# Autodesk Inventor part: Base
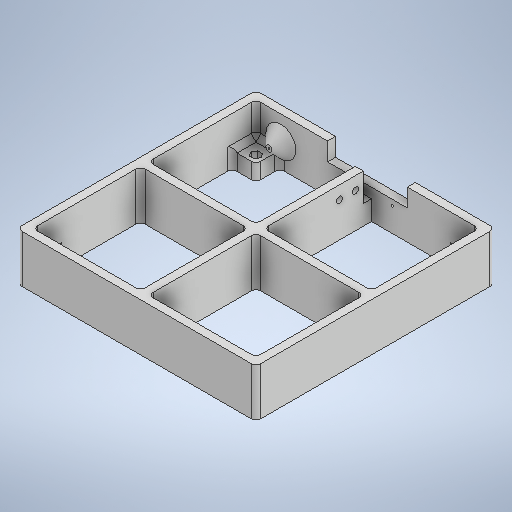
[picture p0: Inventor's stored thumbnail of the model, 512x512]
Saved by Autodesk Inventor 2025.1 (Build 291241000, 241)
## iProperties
Created: 2023-12
Part Number: Base
Material: Generic
Document SubType Name: Modeling
Designer: Andrew
Density: 1 g/cm^3
Appearance: Default
Author: Andrew
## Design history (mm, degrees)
sketch "Sketch1"
  geometry: L1 (76.2, -76.2)-(-76.2, -76.2); L2 (-76.2, -76.2)-(-76.2, 76.2); L3 (-76.2, 76.2)-(76.2, 76.2); L4 (76.2, 76.2)-(76.2, -76.2); 1 further point
  constraints: 8 end point, 2 parallel, 1 horizontal, 1 perpendicular
  dimensions: "d0" = 152.4 distance between parallel lines of L3 L1 (derived); "d1" = 152.4 distance between parallel lines of L4 L2; "d2" = 76.2 distance from line of point (0, 0) L1 (= 0.5 x d0); "d3" = 76.2 distance from line of L2 point (0, 0) (= 0.5 x d1)
extrude "Extrusion1" new body sketch "Sketch1" distance "d4" = 5.08; taper "d5" = 0 deg
sketch "Sketch2"
  geometry: L1 (-76.2, -76.2)-(76.2, -76.2) reference; L2 (76.2, -76.2)-(76.2, 76.2) reference; L3 (76.2, 76.2)-(-76.2, 76.2) reference; L4 (-76.2, 76.2)-(-76.2, -76.2) reference; L5 (-71.12, 71.12)-(71.12, 71.12); L6 (71.12, 71.12)-(71.12, -71.12); L7 (71.12, -71.12)-(-71.12, -71.12); L8 (-71.12, -71.12)-(-71.12, 71.12); L9 (-71.12, 2.54)-(71.12, 2.54); L10 (71.12, 2.54)-(71.12, -2.54); L11 (71.12, -2.54)-(-71.12, -2.54); L12 (-71.12, -2.54)-(-71.12, 2.54); L13 (-2.54, 71.12)-(2.54, 71.12); L14 (2.54, 71.12)-(2.54, -71.12); L15 (2.54, -71.12)-(-2.54, -71.12); L16 (-2.54, -71.12)-(-2.54, 71.12); 11 further points
  constraints: 24 end point, 6 parallel, 4 point on line, 3 horizontal, 3 perpendicular, 2 midpoint
  dimensions: "d6" = 5.08 distance between parallel lines of L5 L3; "d7" = 5.08 distance between parallel lines of L4 L8; "d8" = 5.08 distance between parallel lines of L2 L6; "d9" = 5.08 distance between parallel lines of L1 L7; "d10" = 5.08 distance between parallel lines of L11 L9; "d11" = 5.08 distance between parallel lines of L16 L14; "d207" = 152.4 distance between parallel lines of L1 L3 (derived); "d208" = 76.2 distance from line of L1 point (-71.12, 0) (derived); "d209" = 76.2 distance from line of point (0, -71.12) L4 (derived)
extrude "Extrusion2" join sketch "Sketch2" distance "d14" = 25.4; taper "d15" = 0 deg
sketch "Sketch3"
  geometry: L1 (0, 30.48)-(152.4, 30.48) reference; L2 (104.14, 30.48)-(93.98, 30.48); L3 (93.98, 30.48)-(93.98, -19.05); L4 (93.98, -19.05)-(104.14, -19.05); L5 (104.14, -19.05)-(104.14, 30.48); L6 (58.42, 30.48)-(48.26, 30.48); L7 (48.26, 30.48)-(48.26, -19.05); L8 (48.26, -19.05)-(58.42, -19.05); L9 (58.42, -19.05)-(58.42, 30.48); L10 (152.4, 0)-(152.4, 30.48) reference; L11 (0, 0)-(152.4, 0) reference; 7 further points
  constraints: 16 end point, 5 midpoint, 4 parallel, 3 point on line, 2 horizontal, 2 perpendicular
  dimensions: "d18" = 10.16 distance from line of L3 point (104.14, 5.715); "d19" = 10.16 distance from line of L7 point (58.42, 5.715); "d20" = 35.56 distance between parallel lines of L9 L3; "d173" = 19.05 distance between parallel lines of L11 L4; "d198" = 17.78 distance from line of point (76.2, 30.48) L3 (derived)
extrude "Extrusion3" join sketch "Sketch3" distance "d23" = 38.1; taper "d24" = 0 deg
sketch "Sketch4"
  geometry: L1 (93.98, 30.48)-(93.98, -19.05) reference; L2 (93.98, 25.4)-(58.42, 25.4); L3 (58.42, 25.4)-(58.42, 30.48); L4 (58.42, 30.48)-(93.98, 30.48); L5 (93.98, 30.48)-(93.98, 25.4); L6 (58.42, -19.05)-(58.42, 30.48) reference; L7 (58.42, 30.48)-(93.98, 30.48) reference; 2 further points
  constraints: 8 end point, 2 parallel, 1 horizontal, 1 perpendicular, 1 point on line
  dimensions: "d25" = 0 distance between parallel lines of L6 L3; "d26" = 0 distance between parallel lines of L7 L4; "d27" = 5.08 distance between parallel lines of L4 L2
extrude "Extrusion4" join sketch "Sketch4" stored distance "d28" = 25.4; taper "d29" = 0 deg
sketch "Sketch5"
  geometry: L1 (7.62, -33.02)-(48.26, -33.02); L2 (48.26, -33.02)-(48.26, 0); L3 (48.26, 0)-(7.62, 0); L4 (7.62, 0)-(7.62, -33.02); L5 (104.14, 0)-(-48.26, 0) reference; L6 (10.16, -38.1)-(0, -38.1) reference; L7 (45.72, -38.1)-(10.16, -38.1) reference; 6 further points; 2 other entities
  constraints: 8 end point, 2 parallel, 1 horizontal, 1 midpoint, 1 perpendicular, 2 other
  dimensions: "d32" = 33.02 distance between parallel lines of L1 L3; "d174" = 2.54 dimension on L4; "d175" = 2.54 dimension on L2; "d177" = 38.1 distance between parallel lines of L6 L3
extrude "Extrusion5" cut sketch "Sketch5" distance "d34" = 2.54; taper "d35" = 0 deg
sketch "Sketch8"
  geometry: L1 (55.88, 25.4)-(96.52, 25.4); L2 (96.52, 25.4)-(96.52, 19.812); L3 (96.52, 19.812)-(55.88, 19.812); L4 (55.88, 19.812)-(55.88, 25.4); L5 (58.42, -19.05)-(58.42, 25.4) reference; L6 (93.98, 25.4)-(93.98, -19.05) reference; L7 (96.52, 11.684)-(55.88, 11.684); L8 (55.88, 11.684)-(55.88, 17.272); L9 (55.88, 17.272)-(96.52, 17.272); L10 (96.52, 17.272)-(96.52, 11.684); L11 (96.52, 3.556)-(55.88, 3.556); L12 (55.88, 3.556)-(55.88, 9.144); L13 (55.88, 9.144)-(96.52, 9.144); L14 (96.52, 9.144)-(96.52, 3.556); L15 (96.52, -4.572)-(55.88, -4.572); L16 (55.88, -4.572)-(55.88, 1.016); L17 (55.88, 1.016)-(96.52, 1.016); L18 (96.52, 1.016)-(96.52, -4.572); L19 (96.52, -12.7)-(55.88, -12.7); L20 (55.88, -12.7)-(55.88, -7.112); L21 (55.88, -7.112)-(96.52, -7.112); L22 (96.52, -7.112)-(96.52, -12.7); L23 (96.52, -15.24)-(55.88, -15.24); L24 (55.88, -15.24)-(55.88, -20.828); L25 (55.88, -20.828)-(96.52, -20.828); L26 (96.52, -20.828)-(96.52, -15.24); L27 (96.52, -28.956)-(55.88, -28.956); L28 (55.88, -28.956)-(55.88, -23.368); L29 (55.88, -23.368)-(96.52, -23.368); L30 (96.52, -23.368)-(96.52, -28.956); L31 (96.52, -37.084)-(55.88, -37.084); L32 (55.88, -37.084)-(55.88, -31.496); L33 (55.88, -31.496)-(96.52, -31.496); L34 (96.52, -31.496)-(96.52, -37.084); 15 further points
  constraints: 64 end point, 16 parallel, 13 collinear, 8 horizontal, 8 perpendicular, 2 midpoint, 2 other
  dimensions: "d39" = 5.588 dimension on L3; "d40" = 2.54 distance between parallel lines of L5 L4; "d41" = 2.54 distance between parallel lines of L6 L2; "d117" = 5.588 distance between parallel lines of L9 L7 (= d39); "d119" = 2.54 distance between parallel lines of L3 L9; "d120" = 2.54 distance between parallel lines of L7 L13 (= d119); "d121" = 5.588 distance between parallel lines of L13 L11 (= d117); "d122" = 5.588 distance between parallel lines of L17 L15 (= d121); "d123" = 2.54 distance between parallel lines of L11 L17 (= d120); "d178" = 5.588 distance between parallel lines of L21 L19 (derived); "d179" = 2.54 distance between parallel lines of L15 L21 (derived); "d180" = 5.588 distance from line of point (76.2, -15.24) L25 (derived); "d181" = 2.54 distance between parallel lines of L19 L23 (derived); "d199" = 2.54 distance from line of point (55.88, -18.034) L5 (derived); "d200" = 5.588 distance between parallel lines of L29 L27 (derived); "d201" = 5.588 distance between parallel lines of L33 L31 (derived); "d202" = 2.54 distance between parallel lines of L25 L29 (derived); "d203" = 2.54 distance between parallel lines of L27 L33 (derived)
extrude "Extrusion7" cut sketch "Sketch8" stored distance "d42" = 31.75; taper "d43" = 0 deg
fillet "Fillet1" dims "d49" = 3.175
sketch "Sketch10"
  geometry: L1 (2.54, -2.54)-(71.12, -2.54) reference; L2 (71.12, -2.54)-(71.12, -71.12) reference; L3 (71.12, -71.12)-(2.54, -71.12) reference; L4 (2.54, -71.12)-(2.54, -2.54) reference; L5 (71.12, 71.12)-(2.54, 71.12) reference; L6 (2.54, 2.54)-(2.54, 71.12) reference; L7 (2.54, 71.12)-(71.12, 71.12) reference; L8 (71.12, 71.12)-(71.12, 2.54) reference; L9 (71.12, 2.54)-(2.54, 2.54) reference; L10 (-2.54, 2.54)-(-71.12, 2.54) reference; L11 (-71.12, 2.54)-(-71.12, 71.12) reference; L12 (-71.12, 71.12)-(-2.54, 71.12) reference; L13 (-2.54, 71.12)-(-2.54, 2.54) reference; L14 (-2.54, -2.54)-(-2.54, -71.12) reference; L15 (-2.54, -71.12)-(-71.12, -71.12) reference; L16 (-71.12, -71.12)-(-71.12, -2.54) reference; L17 (-71.12, -2.54)-(-2.54, -2.54) reference; 3 further points
extrude "Extrusion9" cut sketch "Sketch10" distance "d54" = 25.4; taper "d55" = 0 deg
sketch "Sketch12" dims "d175" = 2.54
  geometry: L1 (2.54, 71.12)-(71.12, 71.12) reference; L2 (71.12, 71.12)-(55.88, 71.12); L3 (55.88, 71.12)-(55.88, 55.88); L4 (55.88, 55.88)-(71.12, 55.88); L5 (71.12, 55.88)-(71.12, 71.12); L6 (71.12, -71.12)-(2.54, -71.12) reference; L7 (71.12, -71.12)-(55.88, -71.12); L8 (55.88, -71.12)-(55.88, -55.88); L9 (55.88, -55.88)-(71.12, -55.88); L10 (71.12, -55.88)-(71.12, -71.12); L11 (-71.12, 71.12)-(-55.88, 71.12); L12 (-55.88, 71.12)-(-55.88, 55.88); L13 (-55.88, 55.88)-(-71.12, 55.88); L14 (-71.12, 55.88)-(-71.12, 71.12); L15 (-71.12, -71.12)-(-71.12, -2.54) reference; L16 (-71.12, -71.12)-(-55.88, -71.12); L17 (-55.88, -71.12)-(-55.88, -55.88); L18 (-55.88, -55.88)-(-71.12, -55.88); L19 (-71.12, -55.88)-(-71.12, -71.12); L20 (71.12, -2.54)-(71.12, -71.12) reference; L21 (-71.12, 2.54)-(-71.12, 71.12) reference; L22 (71.12, 71.12)-(71.12, 2.54) reference; L23 (76.2, 73.025)-(76.2, -73.025) reference; L24 (-76.2, -73.025)-(-76.2, 73.025) reference; L25 (-73.025, 76.2)-(73.025, 76.2) reference; C1 r 1.905 at (60.96, 60.96); C2 r 1.905 at (60.96, -60.96); C3 r 1.905 at (-60.96, 60.96); C4 r 1.905 at (-60.96, -60.96); 17 further points; 2 other entities
  constraints: 32 end point, 8 parallel, 6 midpoint, 4 centre point, 4 horizontal, 4 perpendicular, 2 other
  dimensions: "d56" = 15.24 distance between parallel lines of L6 L9 (= d82); "d57" = 15.24 distance between parallel lines of L20 L8 (= d58); "d58" = 15.24 distance from line of L15 point (-55.88, -63.5); "d59" = 15.24 distance from line of L16 point (-63.5, -55.88); "d64" = 3.81 diameter of C3; "d65" = 3.81 diameter of C4 (= d64); "d66" = 3.81 diameter of C2 (= d64); "d67" = 3.81 diameter of C1 (= d64); "d78" = 15.24 dimension on C2.centre; "d79" = 15.24 distance from line of L23 C2.centre; "d85" = 15.24 distance from line of point (63.5, 71.12) L4 (= d78); "d86" = 15.24 distance between parallel lines of L5 L3 (= d57); "d87" = 15.24 distance between parallel lines of L14 L12 (= d82); "d88" = 15.24 distance between parallel lines of L13 L11 (= d58); "d89" = 15.24 distance from line of C3.centre L25 (= d82); "d90" = 15.24 dimension on C4.centre (= d78); "d91" = 15.24 distance from line of L24 C4.centre (= d79); "d92" = 15.24 distance from line of L24 C3.centre (= d58); "d93" = 15.24 distance from line of L23 C1.centre (= d57); "d94" = 15.24 distance from line of L25 C1.centre (= d78)
extrude "Extrusion10" join sketch "Sketch12" stored distance "d76" = 25.4; taper "d77" = 0 deg
fillet "Fillet2" dims "d95" = 3.175
sketch "Sketch13"
  geometry: L1 (-62.544, -58.217)-(-59.376, -58.217); L2 (-59.376, -58.217)-(-57.792, -60.96); L3 (-57.792, -60.96)-(-59.376, -63.703); L4 (-59.376, -63.703)-(-62.544, -63.703); L5 (-62.544, -63.703)-(-64.128, -60.96); L6 (-64.128, -60.96)-(-62.544, -58.217); L7 (-59.376, 63.703)-(-57.792, 60.96); L8 (-57.792, 60.96)-(-59.376, 58.217); L9 (-59.376, 58.217)-(-62.544, 58.217); L10 (-62.544, 58.217)-(-64.128, 60.96); L11 (-64.128, 60.96)-(-62.544, 63.703); L12 (-62.544, 63.703)-(-59.376, 63.703); L13 (59.376, 63.703)-(62.544, 63.703); L14 (62.544, 63.703)-(64.128, 60.96); L15 (64.128, 60.96)-(62.544, 58.217); L16 (62.544, 58.217)-(59.376, 58.217); L17 (59.376, 58.217)-(57.792, 60.96); L18 (57.792, 60.96)-(59.376, 63.703); L19 (59.376, -58.217)-(62.544, -58.217); L20 (62.544, -58.217)-(64.128, -60.96); L21 (64.128, -60.96)-(62.544, -63.703); L22 (62.544, -63.703)-(59.376, -63.703); L23 (59.376, -63.703)-(57.792, -60.96); L24 (57.792, -60.96)-(59.376, -58.217); C1 r 1.905 at (-60.96, -60.96) reference; C2 r 1.905 at (-60.96, 60.96) reference; C3 r 1.905 at (60.96, 60.96) reference; C4 r 1.905 at (60.96, -60.96) reference; 6 further points
  constraints: 48 end point, 4 coincident, 4 horizontal, 1 midpoint, 52 other
  dimensions: "d96" = 5.4864 distance between parallel lines of L21 L24; "d97" = 5.4864 distance between parallel lines of L15 L18 (= d96); "d98" = 5.4864 distance from line of point (-58.584, 59.588) L11 (= d96); "d99" = 5.4864 distance between parallel lines of L3 L6 (= d96)
extrude "Extrusion11" cut sketch "Sketch13" distance "d100" = 25.4; taper "d101" = 0 deg
sketch "Sketch22"
  geometry: L1 (52.705, 0)-(-3.175, 0) reference; L2 (49.53, 0)-(49.53, -34.925) reference; L3 (0, 0)-(49.53, 0); L4 (49.53, 0)-(49.53, -5.08); L5 (49.53, -5.08)-(0, -5.08); L6 (0, -5.08)-(0, 0); L7 (0, -34.925)-(0, 0) reference; 4 further points
  constraints: 8 end point, 2 parallel, 2 point on line, 1 horizontal, 1 perpendicular
  dimensions: "d182" = 0 distance between parallel lines of L7 L6; "d183" = 5.08 distance between parallel lines of L3 L5
extrude "Extrusion19" join sketch "Sketch22" stored distance "d184" = 25.4; taper "d185" = 0 deg
chamfer "Chamfer2" distance "d124" = 2.286; stored, may be unused: second distance "d125" = 3.175, angle "d126" = 45 deg
sketch "Sketch17"
  geometry: L1 (-12.7, 114.3)-(12.7, 114.3); L2 (12.7, 114.3)-(12.7, 91.44); L3 (12.7, 91.44)-(-12.7, 91.44); L4 (-12.7, 91.44)-(-12.7, 114.3); L5 (27.94, 79.375)-(27.94, 111.125) reference; L6 (-27.94, 79.375)-(-27.94, 111.125) reference; L7 (-24.765, 114.3)-(24.765, 114.3) reference; 2 further points
  constraints: 8 end point, 2 parallel, 1 horizontal, 1 midpoint, 1 perpendicular
  dimensions: "d141" = 25.4 distance between parallel lines of L2 L4; "d142" = 55.88 distance between parallel lines of L5 L6 (derived); "d143" = 27.94 distance from line of L5 point (0, 114.3) (derived); "d144" = 0 distance between parallel lines of L7 L1; "d145" = 22.86 distance between parallel lines of L3 L1
extrude "Extrusion15" cut sketch "Sketch17" extent not by distance; stored distance "d146" = 0; taper "d147" = 0 deg
fillet "Fillet5" dims "d148" = 3.175
sketch "Sketch28"
  geometry: L1 (-98.881, -146.502)-(84.327, -146.502); L2 (84.327, -146.502)-(84.327, -76.2); L3 (84.327, -76.2)-(-98.881, -76.2); L4 (-98.881, -76.2)-(-98.881, -146.502); L5 (73.025, -76.2)-(31.115, -76.2) reference; 1 further point
  constraints: 8 end point, 2 parallel, 1 horizontal, 1 perpendicular
  dimensions: "d236" = 0 distance between parallel lines of L5 L3
extrude "Extrusion25" cut sketch "Sketch28" extent not by distance; stored distance "d237" = 0; taper "d238" = 0 deg
sketch "Sketch19"
  geometry: L1 (93.345, 1.016)-(93.345, -4.572) reference; L2 (45.085, 0)-(45.085, 30.48) reference; L3 (0, 30.48)-(41.91, 30.48) reference; L4 (0, 0)-(41.91, 0) reference; L5 (104.14, 0)-(146.05, 0) reference; L6 (73.025, -28.956)-(73.025, 40.386) reference; C1 r 0.635 at (128.27, 15.24); C2 r 0.635 at (57.15, 15.24); 10 further points; 1 other entity
  constraints: 2 centre point, 1 midpoint, 2 other
  dimensions: "d156" = 1.27 diameter of C1; "d157" = 1.27 diameter of C2; "d187" = 71.12 distance of C1.centre C2.centre; "d204" = 30.48 distance between parallel lines of L3 L4 (derived); "d205" = 15.24 distance from line of L4 C2.centre (derived); "d206" = 15.24 distance from line of C1.centre L5 (derived); "d235" = 55.245 distance from line of L6 C1.centre
extrude "Extrusion17" cut sketch "Sketch19" distance "d163" = 12.7; taper "d164" = 0 deg
sketch "Sketch23"
  geometry: L1 (46.173, 31.431)-(71.12, 31.431); L2 (71.12, 31.431)-(71.12, 71.12); L3 (71.12, 71.12)-(46.173, 71.12); L4 (46.173, 71.12)-(46.173, 31.431); L5 (46.173, -43.871)-(71.12, -43.871); L6 (71.12, -43.871)-(71.12, -71.12); L7 (71.12, -71.12)-(46.173, -71.12); L8 (46.173, -71.12)-(46.173, -43.871); L9 (-32.457, -43.871)-(-71.12, -43.871); L10 (-71.12, -43.871)-(-71.12, -71.12); L11 (-71.12, -71.12)-(-32.457, -71.12); L12 (-32.457, -71.12)-(-32.457, -43.871); L13 (-46.383, 37.781)-(-71.12, 37.781); L14 (-71.12, 37.781)-(-71.12, 71.12); L15 (-71.12, 71.12)-(-46.383, 71.12); L16 (-46.383, 71.12)-(-46.383, 37.781); L17 (2.54, 71.12)-(52.705, 71.12) reference; L18 (71.12, 52.705)-(71.12, 5.715) reference; L19 (52.705, -71.12)-(5.715, -71.12) reference; L20 (-71.12, -52.705)-(-71.12, -5.715) reference; L21 (-71.12, 5.715)-(-71.12, 52.705) reference; L22 (-52.705, 71.12)-(-2.54, 71.12) reference; 3 further points
  constraints: 32 end point, 8 parallel, 6 collinear, 4 horizontal, 4 perpendicular, 4 point on line
extrude "Extrusion20" cut sketch "Sketch23" distance "d191" = 20.32; taper "d192" = 0 deg
fillet "Fillet6" dims "d196" = 3.175
sketch "Sketch25"
  geometry: L1 (25.463, 71.12)-(-25.464, 71.12); L2 (-25.464, 71.12)-(-25.464, 65.913); L3 (-25.464, 65.913)-(25.463, 65.913); L4 (25.463, 65.913)-(25.463, 71.12); L5 (-67.945, 71.12)-(-2.54, 71.12) reference; L6 (73.025, 76.2)-(-73.025, 76.2) reference; 5 further points
  constraints: 8 end point, 3 midpoint, 2 parallel, 1 horizontal, 1 perpendicular
  dimensions: "d212" = 0 distance between parallel lines of L5 L1; "d213" = 5.207 distance between parallel lines of L1 L3; "d214" = 50.927 distance of point (-25.464, 68.516) point (25.463, 68.517); "d215" = 25.4635 horizontal distance of point (0, 76.2) point (25.463, 68.517) (derived)
extrude "Extrusion22" cut sketch "Sketch25" distance "d216" = 17.907; taper "d217" = 0 deg
sketch "Sketch26"
  geometry: L1 (-67.31, 0)-(-67.31, 30.48) reference; L2 (0, 0)-(11.43, 0) reference; L3 (-60.198, 30.48)-(-60.198, 12.573) reference; L4 (-60.198, 30.48)-(0, 30.48) reference; L5 (-70.485, 30.48)-(-70.485, 0) reference; L6 (0, 0)-(-65.405, 0) reference; C1 r 1.905 at (-55.118, 22.225); C2 r 1.905 at (-44.958, 22.225); 2 further points
  constraints: 2 centre point
  dimensions: "d219" = 3.81 diameter of C1; "d224" = 3.81 diameter of C2 (derived); "d233" = 15.367 horizontal distance of C1.centre L5.start; "d234" = 25.527 distance from line of L5 C2.centre; "d250" = 0 vertical distance of C2.centre C1.centre; "d252" = 8.255 distance from line of L4 C1.centre
extrude "Extrusion23" cut sketch "Sketch26" distance "d221" = 12.7; taper "d222" = 0 deg
sketch "Sketch27"
  geometry: L1 (25.463, 99.824)-(-25.464, 99.824); L2 (-25.464, 99.824)-(-25.464, 65.913); L3 (-25.464, 65.913)-(25.463, 65.913); L4 (25.463, 65.913)-(25.463, 99.824); L5 (73.025, 76.2)-(-73.025, 76.2) reference; L6 (2.54, 65.913)-(-2.54, 65.913) reference; 2 further points
  constraints: 8 end point, 2 parallel, 1 horizontal, 1 midpoint, 1 perpendicular
  dimensions: "d229" = 25.4635 distance from line of point (0, 76.2) L4 (derived); "d230" = 50.927 distance between parallel lines of L2 L4; "d246" = 0 distance between parallel lines of L6 L3
extrude "Extrusion24" cut sketch "Sketch27" distance "d231" = 11.557; taper "d232" = 0 deg
sketch "Sketch29"
  geometry: C1 r 0.635 at (-2.54, 15.24) reference; C2 r 1.905 at (-2.54, 15.24); 1 further point
  constraints: 1 centre point, 1 coincident
  dimensions: "d239" = 3.81 diameter of C2
extrude "Extrusion26" join sketch "Sketch29" distance "d241" = 7.62; taper "d242" = 0 deg
chamfer "Chamfer5" distance "d243" = 7.62; stored, may be unused: second distance "d244" = 3.175, angle "d245" = 45 deg
chamfer "Chamfer6" distance "d247" = 3.175; stored, may be unused: second distance "d248" = 3.175, angle "d249" = 45 deg
feature "ଫ耀ଭ耀ଯ耀଱耀ଳ耀ଵ耀ଷ耀ହ耀" dims "d0" = 152.4 (derived), "d1" = 152.4, "d2" = 76.2 (= 0.5 x d0), "d3" = 76.2 (= 0.5 x d1), "d4" = 5.08, "d5" = 0, "d6" = 5.08, "d7" = 5.08, "d8" = 5.08, "d9" = 5.08, "d10" = 5.08, "d11" = 5.08, "d14" = 25.4, "d15" = 0, "d18" = 10.16, "d19" = 10.16, "d20" = 35.56, "d23" = 38.1, "d24" = 0, "d25" = 0, "d26" = 0, "d27" = 5.08, "d28" = 25.4, "d29" = 0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
body "Solid1"
node "Projected Loop1"
node "Projected Loop2"
node "Projected Loop3"
node "Projected Loop4"
node "Projected Loop5"
